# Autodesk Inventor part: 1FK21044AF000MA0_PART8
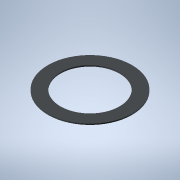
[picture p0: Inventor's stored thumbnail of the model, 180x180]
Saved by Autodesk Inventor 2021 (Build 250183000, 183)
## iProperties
Created: 2025-04
Part Number: 1FK21044AF000MA0_PART8
Material: Generic
Catalog Web Link: www.3dfindit.com
Description: -Servo synchronous motor
Document SubType Name: Modeling
Designer: psAdmin
Mass: 0.27214 g
Surface Area: 11.8752 cm^2
Volume: 0.27214 cm^3
Density: 1 g/cm^3
Appearance: PSOLRGB-212-217-219
Category: PARTsolutions
Title: 1FK21044AF000MA0_PART8
Author: Cadenas PARTsolutions
Comments: Servo synchronous motor
Sending System: PARTsolutions
Preprocessor: ST-DEVELOPER v19.3
PSOL_IDENT_0: {$CADENAS_DATA/23d-libs/siemens_ag/_cat_/39/c4/1fk21044af000ma0.prj},213 {VTYP=3D},{NB=1FK21044AF000
PSOL_IDENT_1: MA0_PART8},{LINA=1FK21044AF000MA0_PART8},{NN=1FK21044AF000MA0_PART8},{NOPRJ=TRUE},{DATE=19.08.2025 1
PSOL_IDENT_2: 4:00:33},{GEOMDATE=30.07.2025 02:02:22},{VERSION=},{LINEID=10},{WBVAR=},{WBNUMERIC=}  {NB=1FK21044AF
PSOL_IDENT_3: 000MA0_PART8},{LINA=1FK21044AF000MA0_PART8},{KT=DUMMY},{PREVIEW=../../../_pool_/cb/72/p_d211_xx_0043
PSOL_IDENT_4: 4j.png},{DESCSHORT=SIMOTICS S-1FK2 HD, SINAMICS S210 3AC 400V-480V, 1.27 Nm, 3000 rpm},{DESCLONG=SIM
PSOL_IDENT_5: OTICS S-1FK2 HD servo motor M0=1.27 Nm; PN = 0.4 kW at nN=3000 rpm (380-480 V); PN = 0.2 kW at nN=15
PSOL_IDENT_6: 00 rpm (200-240 V); degree of protection IP64; cylindrical shaft D19x40mm; absolute encoder 22-bit +
PSOL_IDENT_7: 12-bit multiturn (encoder AM22DQC); with OCC interface; plug size M17, rotatable; SIMOTICS S-1FK2 s
PSOL_IDENT_8: ervomotorfor a wide range of uses in industrial environments. SIMOTICS S‑1FK2 servomotors are compac
PSOL_IDENT_9: t synchronous motors with a high dynamic performance that set themselves apart as a result of their
PSOL_IDENT_10: high power density, degree of protection and overload capability. The motors are available in two va
PSOL_IDENT_11: riants: as High Dynamic variant (highest dynamic performance as a result of the low intrinsic moment
PSOL_IDENT_12: of inertia for applications demanding a high dynamic performance with low moved masses) - and as Co
PSOL_IDENT_13: mpact variant (precise and stable closed-loop control for medium up to large moved masses as a resul
PSOL_IDENT_14: t of a medium intrinsic moment of inertia). SIMOTICSS‑1FK2 servomotors fully exploit their strengths
PSOL_IDENT_15: in a system with the SINAMICSS210 frequency converter and simple connection using the one cable con
PSOL_IDENT_16: nection (OCC). Advantages include the short control and positioning times, fast and precise correcti
PSOL_IDENT_17: on of disturbing quantities as well as stable control with a high dynamic performance. The servo mot
PSOL_IDENT_18: ors can be configured to address a wide range of requirements. For example with and without holding
PSOL_IDENT_19: brake, IP64 or IP65 degree of protection, singleturn or multiturn absolute encoders - to name just a
PSOL_IDENT_20: few. Further, the servomotors are available in different shaft heights extending from 20 to 100. A
PSOL_IDENT_21: shaft sealing ring is available to achieve an IP65 degree of protection and for subsequent mounting
PSOL_IDENT_22: at the motor or as spare part. SIMOTICS - the optimum motor for each and every motion control applic
PSOL_IDENT_23: ation.},{INTNO=804766906428},{SUPPLIERALTNO=1FK2104-4AF00-0MA0},{MANUID=1FK21044AF000MA0},{MANUNAME=
PSOL_IDENT_24: Siemens},{MANUTYPEDESC=Synchronous motor 1FK2-HD 1.27 NM},{AAU732=SIMOTICS},{AAO057=S-1FK2},{AAU734=
PSOL_IDENT_25: SIMOTICS S-1FK2 HD servo motor M0=1.27 Nm; PN = 0.4 kW at nN=3000 rpm (380-480 V); PN = 0.2 kW at nN=
PSOL_IDENT_26: 1500 rpm (200-240 V); degree of protection IP64; cylindrical shaft D19x40mm; absolute encoder 22-bit
PSOL_IDENT_27: + 12-bit multiturn (encoder AM22DQC); with OCC interface; plug size M17, rotatable;},{AAW338=Synchr
PSOL_IDENT_28: onous motor 1FK2-HD 1.27 NM},{AAO742=SIMOTICS},{AAO663=4042948693322},{NOCUPEROU=1},{PRICEQUANTITY=1
PSOL_IDENT_29: },{QUANTITYMIN=1},{QUANTITYINT=1},{CTN=85015100},{COO=DE},{AAO676=1FK2104-4AF00-0MA0},{AAO677=Siemen
PSOL_IDENT_30: s AG},{ORDERUNIT=C62},{CONTENTUNIT=C62}
NB: 1FK21044AF000MA0_PART8
NT: Servo synchronous motor
NBSYN: $MANUID._PART8
LINA: 1FK21044AF000MA0_PART8
CATALOG: SIEMENS
PREVIEW: ../../../_pool_/cb/72/p_d211_xx_00434j.png
DESCSHORT: SIMOTICS S-1FK2 HD, SINAMICS S210 3AC 400V-480V, 1.27 Nm, 3000 rpm
DESCLONG: SIMOTICS S-1FK2 HD servo motor M0=1.27 Nm; PN = 0.4 kW at nN=3000 rpm (380-480 V); PN = 0.2 kW at nN=1500 rpm (200-240 V); degree of protection IP64; cylindrica
INTNO: 804766906428
SUPPLIERALTNO: 1FK2104-4AF00-0MA0
MANUID: 1FK21044AF000MA0
MANUNAME: Siemens
MANUTYPEDESC: Synchronous motor 1FK2-HD 1.27 NM
AAU732: SIMOTICS
AAO057: S-1FK2
AAU734: SIMOTICS S-1FK2 HD servo motor M0=1.27 Nm; PN = 0.4 kW at nN=3000 rpm (380-480 V); PN = 0.2 kW at nN=1500 rpm (200-240 V); degree of protection IP64; cylindrica
AAW338: Synchronous motor 1FK2-HD 1.27 NM
AAO742: SIMOTICS
AAO663: 4042948693322.0
NOCUPEROU: 1
PRICEQUANTITY: 1
QUANTITYMIN: 1
QUANTITYINT: 1
CTN: 85015100
COO: DE
ARTICLENO: 1FK21044AF000MA0_PART8
BOMINFO: 1FK21044AF000MA0_PART8
CREATOR: CADENAS GmbH
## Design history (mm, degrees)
feature "2025_04_17_15_01_28_0038"
body "Solid1"
